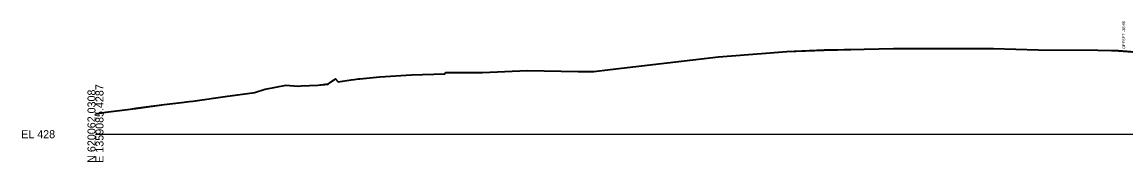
# Model space of a CAD drawing. Extents: x -26 to 803, y -27 to 3586.
# Drawn here: x -25.7 to 360.6, y 1990.3 to 2039.2 of the extents above; entities that cross this region are included whole.
import ezdxf

# ---------------------------------------------------------------- set-up
doc = ezdxf.new("R2010")
doc.units = 0
for name, color, linetype in [('DESIGN - SHEET - Light Grid', 7, 'Continuous'), ('DESIGN - TYPICAL - Slope Tie Text', 7, 'Continuous'), ('SURVEY - GROUND - Bottom of Topsoil Layer', 7, 'Continuous'), ('SURVEY - GROUND - Top of Ground', 7, 'Continuous')]:
    doc.layers.add(name, color=color, linetype=linetype)

msp = doc.modelspace()

# ---------------------------------------------------------------- linework, layer by layer
at = {"layer": 'DESIGN - SHEET - Light Grid'}
msp.add_line((0, 2000), (400, 2000), dxfattribs=at)
at = {"layer": 'SURVEY - GROUND - Bottom of Topsoil Layer'}
for p, q in [((218.03, 2026.97), (234.58, 2028.24)), ((234.58, 2028.24), (241.98, 2028.8)), ((241.98, 2028.8), (255.06, 2029.33)), ((255.06, 2029.33), (269.04, 2029.61)), ((269.04, 2029.61), (279.28, 2029.86)), ((279.28, 2029.86), (281.83, 2029.89)), ((281.83, 2029.89), (284.16, 2029.9)), ((284.16, 2029.9), (302.75, 2029.9)), ((302.75, 2029.9), (314.29, 2029.85)), ((314.29, 2029.85), (329.92, 2029.42)), ((329.92, 2029.42), (350.75, 2029.23)), ((350.75, 2029.23), (355.58, 2029.15)), ((355.58, 2029.15), (358.03, 2029.1)), ((358.03, 2029.1), (369.54, 2028.19)), ((180.07, 2022.5), (218.03, 2026.97)), ((99.55, 2019.97), (110.56, 2020.68)), ((110.56, 2020.68), (122.24, 2020.96)), ((122.24, 2020.96), (122.58, 2021.46)), ((122.58, 2021.46), (135.48, 2021.48)), ((135.48, 2021.48), (151.12, 2022.11)), ((151.12, 2022.11), (168.87, 2021.8)), ((168.87, 2021.8), (174.39, 2021.79)), ((174.39, 2021.79), (180.07, 2022.5)), ((59.4, 2015.67), (66.61, 2017.05)), ((66.61, 2017.05), (70.9, 2016.66)), ((70.9, 2016.66), (71.98, 2016.76)), ((71.98, 2016.76), (77.82, 2017.03)), ((77.82, 2017.03), (81.38, 2017.43)), ((81.38, 2017.43), (82.03, 2017.97)), ((82.03, 2017.97), (83.97, 2019.22)), ((83.97, 2019.22), (84.96, 2018.19)), ((84.96, 2018.19), (89.43, 2018.85)), ((89.43, 2018.85), (90.56, 2018.99)), ((90.56, 2018.99), (92.1, 2019.25)), ((92.1, 2019.25), (92.48, 2019.27)), ((92.48, 2019.27), (99.55, 2019.97)), ((34.06, 2011.47), (45.37, 2013.04)), ((45.37, 2013.04), (55.82, 2014.43)), ((55.82, 2014.43), (59.4, 2015.67)), ((12.13, 2008.64), (14.13, 2008.92)), ((14.13, 2008.92), (24.02, 2010.23)), ((24.02, 2010.23), (30.14, 2010.94)), ((30.14, 2010.94), (32.77, 2011.31)), ((32.77, 2011.31), (34.06, 2011.47)), ((0, 2006.96), (3.63, 2007.56)), ((3.63, 2007.56), (12.13, 2008.64))]:
    msp.add_line(p, q, dxfattribs=at)
at = {"layer": 'SURVEY - GROUND - Top of Ground'}
msp.add_lwpolyline([(0, 2007.21), (3.63, 2007.81), (12.13, 2008.89), (14.13, 2009.17), (24.02, 2010.48), (30.14, 2011.19), (32.77, 2011.56), (34.06, 2011.72), (45.37, 2013.29), (55.82, 2014.68), (59.4, 2015.92), (66.61, 2017.3), (70.9, 2016.91), (71.98, 2017.01), (77.82, 2017.28), (81.38, 2017.68), (82.03, 2018.22), (83.97, 2019.47), (84.96, 2018.44), (89.43, 2019.1), (90.56, 2019.24), (92.1, 2019.5), (92.48, 2019.52), (99.55, 2020.22), (110.56, 2020.93), (122.24, 2021.21), (122.58, 2021.71), (135.48, 2021.73), (151.12, 2022.36), (168.87, 2022.05), (174.39, 2022.04), (180.07, 2022.75), (218.03, 2027.22), (234.58, 2028.49), (241.98, 2029.05), (255.06, 2029.58), (269.04, 2029.86), (279.28, 2030.11), (281.83, 2030.14), (284.16, 2030.15), (302.75, 2030.15), (314.29, 2030.1), (329.92, 2029.67), (350.75, 2029.48), (355.58, 2029.4), (358.03, 2029.35), (369.54, 2028.44)], dxfattribs=at)

# ---------------------------------------------------------------- texts
at = {"layer": 'DESIGN - SHEET - Light Grid'}
for s, p in [('E 1359085.4287', (2.8, 1990)), ('N 620062.0308', (0, 1990))]:
    msp.add_text(s, height=2.8, rotation=90, dxfattribs=at).set_placement(p)
msp.add_text('EL 428', height=2.8, dxfattribs=at).set_placement((-26, 1998.6))
at = {"layer": 'DESIGN - TYPICAL - Slope Tie Text'}
msp.add_text('OFFSET -38.65', height=1, rotation=90, dxfattribs=at).set_placement((360.35, 2029.84))

doc.saveas('drawing.dxf')
